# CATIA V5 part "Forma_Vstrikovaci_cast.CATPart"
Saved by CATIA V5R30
Part number: Forma_Vstrikovaci_cast
Publications: "TapHole_CapScrew_E1200_2.3_", "TapHole_CapScrew_E1200_2.4_"
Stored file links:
  E:\Bakalarka\Model\Forma_v7\Forma_Vstrikovaci_cast.CATPart
  E:\Bakalarka\Model\Forma_v7\Forma.CATProduct
  E:\Bakalarka\Model\Forma_v7\TlgItf_Vstrikovaci_cast.CATProduct
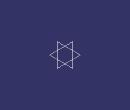
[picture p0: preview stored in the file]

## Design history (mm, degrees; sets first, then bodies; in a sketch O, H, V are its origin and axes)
Body1 (main body)
Body2 "TapHole"
  Solid1: linked copy from another document
Body3 "TapHole"
  Solid2: linked copy from another document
